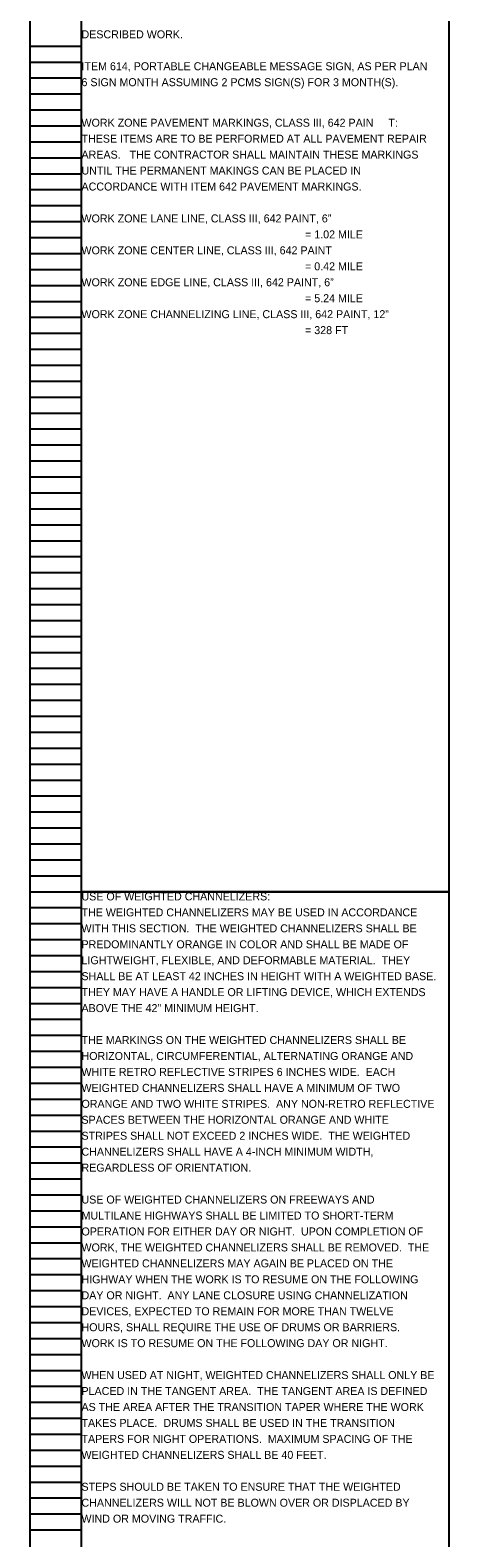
# Model space of a CAD drawing. Extents: x 16463 to 16500, y 5400 to 5823.
# Drawn here: x 16463.05 to 16470.39, y 5691.17 to 5717.63 of the extents above; entities that cross this region are included whole.
import ezdxf

# ---------------------------------------------------------------- set-up
doc = ezdxf.new("R2010")
doc.units = 0
for name, color, linetype in [('Default', 7, 'Continuous'), ('SC_Scratch1', 7, 'Continuous'), ('SH_Data', 7, 'Continuous')]:
    doc.layers.add(name, color=color, linetype=linetype)

msp = doc.modelspace()

# ---------------------------------------------------------------- linework, layer by layer
at = {"layer": 'SC_Scratch1'}
for points in [[(16463.949, 5722.672), (16470.389, 5722.672), (16470.389, 5702.512), (16463.949, 5702.512)], [(16463.949, 5702.512), (16470.389, 5702.512), (16470.389, 5682.352), (16463.949, 5682.352)]]:
    msp.add_lwpolyline(points, close=True, dxfattribs=at)
at = {"layer": 'SH_Data'}
for p, q in [((16463.049, 5702.512), (16463.049, 5722.672)), ((16463.949, 5702.512), (16463.949, 5722.672)), ((16463.049, 5717.352), (16463.949, 5717.352)), ((16463.049, 5717.072), (16463.949, 5717.072)), ((16463.049, 5716.792), (16463.949, 5716.792)), ((16463.049, 5716.512), (16463.949, 5716.512)), ((16463.049, 5716.232), (16463.949, 5716.232)), ((16463.049, 5715.952), (16463.949, 5715.952)), ((16463.049, 5715.672), (16463.949, 5715.672)), ((16463.049, 5715.392), (16463.949, 5715.392)), ((16463.049, 5715.112), (16463.949, 5715.112)), ((16463.049, 5714.832), (16463.949, 5714.832)), ((16463.049, 5714.552), (16463.949, 5714.552)), ((16463.049, 5714.272), (16463.949, 5714.272)), ((16463.049, 5713.992), (16463.949, 5713.992)), ((16463.049, 5713.712), (16463.949, 5713.712)), ((16463.049, 5713.432), (16463.949, 5713.432)), ((16463.049, 5713.152), (16463.949, 5713.152)), ((16463.049, 5712.872), (16463.949, 5712.872)), ((16463.049, 5712.592), (16463.949, 5712.592)), ((16463.049, 5712.312), (16463.949, 5712.312)), ((16463.049, 5712.032), (16463.949, 5712.032)), ((16463.049, 5711.752), (16463.949, 5711.752)), ((16463.049, 5711.472), (16463.949, 5711.472)), ((16463.049, 5711.192), (16463.949, 5711.192)), ((16463.049, 5710.912), (16463.949, 5710.912)), ((16463.049, 5710.632), (16463.949, 5710.632)), ((16463.049, 5710.352), (16463.949, 5710.352)), ((16463.049, 5710.072), (16463.949, 5710.072)), ((16463.049, 5709.792), (16463.949, 5709.792)), ((16463.049, 5709.512), (16463.949, 5709.512)), ((16463.049, 5709.232), (16463.949, 5709.232)), ((16463.049, 5708.952), (16463.949, 5708.952)), ((16463.049, 5708.672), (16463.949, 5708.672)), ((16463.049, 5708.392), (16463.949, 5708.392)), ((16463.049, 5708.112), (16463.949, 5708.112)), ((16463.049, 5707.832), (16463.949, 5707.832)), ((16463.049, 5707.552), (16463.949, 5707.552)), ((16463.049, 5707.272), (16463.949, 5707.272)), ((16463.049, 5706.992), (16463.949, 5706.992)), ((16463.049, 5706.712), (16463.949, 5706.712)), ((16463.049, 5706.432), (16463.949, 5706.432)), ((16463.049, 5706.152), (16463.949, 5706.152)), ((16463.049, 5705.872), (16463.949, 5705.872)), ((16463.049, 5705.592), (16463.949, 5705.592)), ((16463.049, 5705.312), (16463.949, 5705.312)), ((16463.049, 5705.032), (16463.949, 5705.032)), ((16463.049, 5704.752), (16463.949, 5704.752)), ((16463.049, 5704.472), (16463.949, 5704.472)), ((16463.049, 5704.192), (16463.949, 5704.192)), ((16463.049, 5703.912), (16463.949, 5703.912)), ((16463.049, 5703.632), (16463.949, 5703.632)), ((16463.049, 5703.352), (16463.949, 5703.352)), ((16463.049, 5703.072), (16463.949, 5703.072)), ((16463.049, 5702.792), (16463.949, 5702.792)), ((16463.049, 5682.352), (16463.049, 5702.512)), ((16463.049, 5702.512), (16463.949, 5702.512)), ((16463.049, 5702.512), (16463.949, 5702.512)), ((16463.949, 5682.352), (16463.949, 5702.512)), ((16463.049, 5702.232), (16463.949, 5702.232)), ((16463.049, 5701.952), (16463.949, 5701.952)), ((16463.049, 5701.672), (16463.949, 5701.672)), ((16463.049, 5701.392), (16463.949, 5701.392)), ((16463.049, 5701.112), (16463.949, 5701.112)), ((16463.049, 5700.832), (16463.949, 5700.832)), ((16463.049, 5700.552), (16463.949, 5700.552)), ((16463.049, 5700.272), (16463.949, 5700.272)), ((16463.049, 5699.992), (16463.949, 5699.992)), ((16463.049, 5699.712), (16463.949, 5699.712)), ((16463.049, 5699.432), (16463.949, 5699.432)), ((16463.049, 5699.152), (16463.949, 5699.152)), ((16463.049, 5698.872), (16463.949, 5698.872)), ((16463.049, 5698.592), (16463.949, 5698.592)), ((16463.049, 5698.312), (16463.949, 5698.312)), ((16463.049, 5698.032), (16463.949, 5698.032)), ((16463.049, 5697.752), (16463.949, 5697.752)), ((16463.049, 5697.472), (16463.949, 5697.472)), ((16463.049, 5697.192), (16463.949, 5697.192)), ((16463.049, 5696.912), (16463.949, 5696.912)), ((16463.049, 5696.632), (16463.949, 5696.632)), ((16463.049, 5696.352), (16463.949, 5696.352)), ((16463.049, 5696.072), (16463.949, 5696.072)), ((16463.049, 5695.792), (16463.949, 5695.792)), ((16463.049, 5695.512), (16463.949, 5695.512)), ((16463.049, 5695.232), (16463.949, 5695.232)), ((16463.049, 5694.952), (16463.949, 5694.952)), ((16463.049, 5694.672), (16463.949, 5694.672)), ((16463.049, 5694.392), (16463.949, 5694.392)), ((16463.049, 5694.112), (16463.949, 5694.112)), ((16463.049, 5693.832), (16463.949, 5693.832)), ((16463.049, 5693.552), (16463.949, 5693.552)), ((16463.049, 5693.272), (16463.949, 5693.272)), ((16463.049, 5692.992), (16463.949, 5692.992)), ((16463.049, 5692.712), (16463.949, 5692.712)), ((16463.049, 5692.432), (16463.949, 5692.432)), ((16463.049, 5692.152), (16463.949, 5692.152)), ((16463.049, 5691.872), (16463.949, 5691.872)), ((16463.049, 5691.592), (16463.949, 5691.592)), ((16463.049, 5691.312), (16463.949, 5691.312))]:
    msp.add_line(p, q, dxfattribs=at)

# ---------------------------------------------------------------- texts
at = {"layer": 'Default'}
for s, p in [('DESCRIBED WORK. ', (16463.949, 5717.488)), ('ITEM 614, PORTABLE CHANGEABLE MESSAGE SIGN, AS PER PLAN ', (16463.949, 5716.928)), ('6 SIGN MONTH ASSUMING 2 PCMS SIGN(S) FOR 3 MONTH(S).', (16463.949, 5716.648)), ('WORK ZONE PAVEMENT MARKINGS, CLASS III, 642 PAIN', (16463.949, 5715.937)), ('T:', (16469.329, 5715.937)), ('THESE ITEMS ARE TO BE PERFORMED AT ALL PAVEMENT REPAIR ', (16463.949, 5715.657)), ('AREAS.   THE CONTRACTOR SHALL MAINTAIN THESE MARKINGS ', (16463.949, 5715.377)), ('UNTIL THE PERMANENT MAKINGS CAN BE PLACED IN ', (16463.949, 5715.097)), ('ACCORDANCE WITH ITEM 642 PAVEMENT MARKINGS. ', (16463.949, 5714.817)), ('WORK ZONE LANE LINE, CLASS III, 642 PAINT, 6”         ', (16463.949, 5714.257)), ('= 1.02 MILE', (16467.869, 5713.977)), ('WORK ZONE CENTER LINE, CLASS III, 642 PAINT         ', (16463.949, 5713.697)), ('= 0.42 MILE', (16467.869, 5713.417)), ('WORK ZONE EDGE LINE, CLASS III, 642 PAINT, 6”', (16463.949, 5713.137)), ('= 5.24 MILE', (16467.869, 5712.857)), ('WORK ZONE CHANNELIZING LINE, CLASS III, 642 PAINT, 12”  ', (16463.949, 5712.577)), ('= 328 FT', (16467.869, 5712.297)), ('USE OF WEIGHTED CHANNELIZERS:', (16463.949, 5702.359)), ('THE WEIGHTED CHANNELIZERS MAY BE USED IN ACCORDANCE ', (16463.949, 5702.079)), ('WITH THIS SECTION.  THE WEIGHTED CHANNELIZERS SHALL BE ', (16463.949, 5701.799)), ('PREDOMINANTLY ORANGE IN COLOR AND SHALL BE MADE OF ', (16463.949, 5701.519)), ('LIGHTWEIGHT, FLEXIBLE, AND DEFORMABLE MATERIAL.  THEY ', (16463.949, 5701.239)), ('SHALL BE AT LEAST 42 INCHES IN HEIGHT WITH A WEIGHTED BASE.  ', (16463.949, 5700.959)), ('THEY MAY HAVE A HANDLE OR LIFTING DEVICE, WHICH EXTENDS ', (16463.949, 5700.679)), ('ABOVE THE 42" MINIMUM HEIGHT.', (16463.949, 5700.399)), ('THE MARKINGS ON THE WEIGHTED CHANNELIZERS SHALL BE ', (16463.949, 5699.839)), ('HORIZONTAL, CIRCUMFERENTIAL, ALTERNATING ORANGE AND ', (16463.949, 5699.559)), ('WHITE RETRO REFLECTIVE STRIPES 6 INCHES WIDE.  EACH ', (16463.949, 5699.279)), ('WEIGHTED CHANNELIZERS SHALL HAVE A MINIMUM OF TWO ', (16463.949, 5698.999)), ('ORANGE AND TWO WHITE STRIPES.  ANY NON-RETRO REFLECTIVE ', (16463.949, 5698.719)), ('SPACES BETWEEN THE HORIZONTAL ORANGE AND WHITE ', (16463.949, 5698.439)), ('STRIPES SHALL NOT EXCEED 2 INCHES WIDE.  THE WEIGHTED ', (16463.949, 5698.159)), ('CHANNELIZERS SHALL HAVE A 4-INCH MINIMUM WIDTH, ', (16463.949, 5697.879)), ('REGARDLESS OF ORIENTATION.', (16463.949, 5697.599)), ('USE OF WEIGHTED CHANNELIZERS ON FREEWAYS AND ', (16463.949, 5697.039)), ('MULTILANE HIGHWAYS SHALL BE LIMITED TO SHORT-TERM ', (16463.949, 5696.759)), ('OPERATION FOR EITHER DAY OR NIGHT.  UPON COMPLETION OF ', (16463.949, 5696.479)), ('WORK, THE WEIGHTED CHANNELIZERS SHALL BE REMOVED.  THE ', (16463.949, 5696.199)), ('WEIGHTED CHANNELIZERS MAY AGAIN BE PLACED ON THE ', (16463.949, 5695.919)), ('HIGHWAY WHEN THE WORK IS TO RESUME ON THE FOLLOWING ', (16463.949, 5695.639)), ('DAY OR NIGHT.  ANY LANE CLOSURE USING CHANNELIZATION ', (16463.949, 5695.359)), ('DEVICES, EXPECTED TO REMAIN FOR MORE THAN TWELVE ', (16463.949, 5695.079)), ('HOURS, SHALL REQUIRE THE USE OF DRUMS OR BARRIERS.  ', (16463.949, 5694.799)), ('WORK IS TO RESUME ON THE FOLLOWING DAY OR NIGHT.', (16463.949, 5694.519)), ('WHEN USED AT NIGHT, WEIGHTED CHANNELIZERS SHALL ONLY BE ', (16463.949, 5693.959)), ('PLACED IN THE TANGENT AREA.  THE TANGENT AREA IS DEFINED ', (16463.949, 5693.679)), ('AS THE AREA AFTER THE TRANSITION TAPER WHERE THE WORK ', (16463.949, 5693.399)), ('TAKES PLACE.  DRUMS SHALL BE USED IN THE TRANSITION ', (16463.949, 5693.119)), ('TAPERS FOR NIGHT OPERATIONS.  MAXIMUM SPACING OF THE ', (16463.949, 5692.839)), ('WEIGHTED CHANNELIZERS SHALL BE 40 FEET.', (16463.949, 5692.559)), ('STEPS SHOULD BE TAKEN TO ENSURE THAT THE WEIGHTED ', (16463.949, 5691.999)), ('CHANNELIZERS WILL NOT BE BLOWN OVER OR DISPLACED BY ', (16463.949, 5691.719)), ('WIND OR MOVING TRAFFIC.  ', (16463.949, 5691.439))]:
    msp.add_text(s, height=0.14, dxfattribs=at).set_placement(p)

doc.saveas('drawing.dxf')
